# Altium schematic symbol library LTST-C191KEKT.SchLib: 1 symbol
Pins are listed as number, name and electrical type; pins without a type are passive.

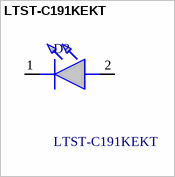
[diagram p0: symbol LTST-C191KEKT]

## LTST-C191KEKT
designator D?
Standard LEDs - SMD SMD LED Thin Red 621nm 60mcd; Manufacturer_Name: Lite-On; Geometry.Height: 0.65mm
footprint LTSTC191KEKT
pins: 1 K, 2 A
